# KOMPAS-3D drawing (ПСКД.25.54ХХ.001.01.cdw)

Views: Вид 1
Referenced files in E:\Work case\Шкаф СУ-001\: Фальшпанель (доработка).cdw
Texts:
  ПСКД.25.54ХХ.001.01
  Фальшпанель (доработка)
  Гайнутдинов З.Х.
  Лист
  Изм.
  № докум.
  Подп.
  Дата
  Инв. № подл.
  Подп. и дата
  Взам. инв. №
  Инв. № дубл.
  *Размеры для справок.
  Неуказанные предельные отклонения размеров: H14,  IT14 2 .
  Место размещения болта заземления не регламентировано
  производителем. В случаях наложения на болт заземления
  комплектующих изделий при сборке шкафа, болт срезать. Приварить в
  ближайшем удобном месте болт М6х20, предварительно просверлив
  отверстие  6,5 мм. Место контакта зачистить от краски с обратной
  стороны фальшпанели.
  Входит в состав
  Таблица исполнений
  ШСУ-54-22-01
  ПСКД.25.5422.001.01
  ПСКД.25.5422.001.01 (ШСУ-5422-01)
  Стандартные изделия
  Винт А2.М4-6gx6 ГОСТ 17473-80
  Фальшпанель
  (доработка)
  Артюхина Е.С.
  Журавлёв А.А.
  Науменко Т.В.
  Нач. отд.
  Ещенко С.Н.
  ЗАО "Промсервис"
  г. Димитровград
  Шкаф
  ЩМП-40-60-19-IP54
  ШСУ БМВ-
Dimensions and other numbers on the sheet: 2; 1:4; 3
